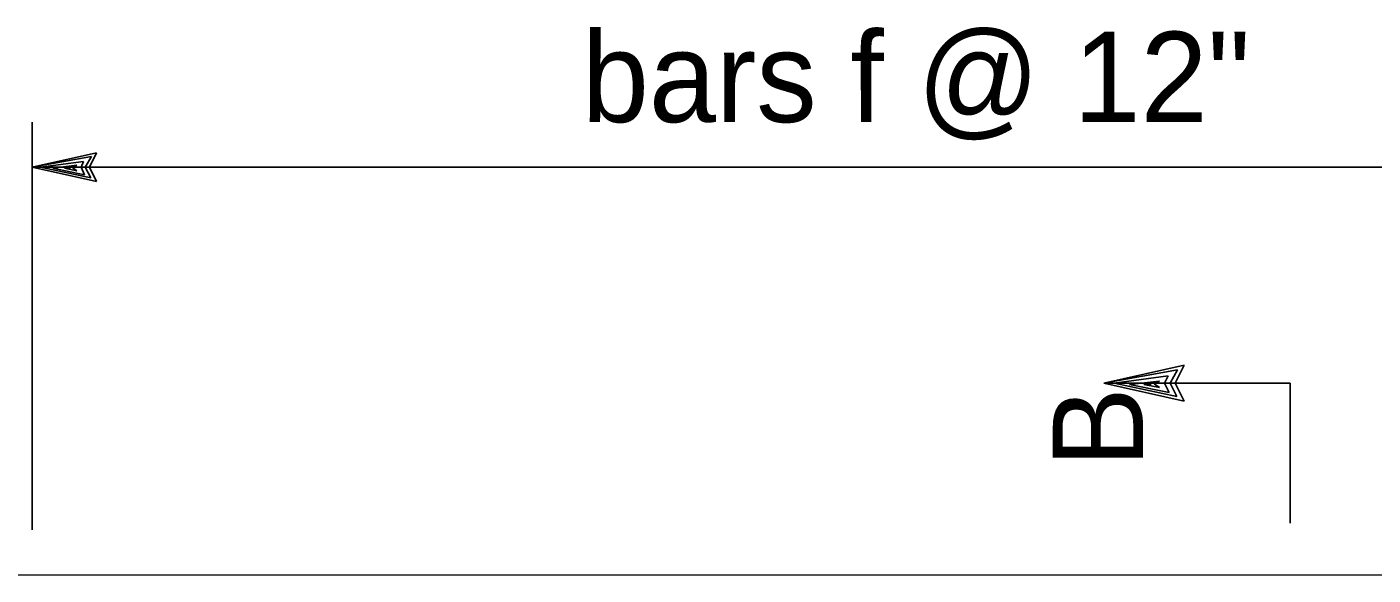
# Model space of a CAD drawing. Extents: x -0.08 to 2.83, y -0.03 to 1.92.
# Drawn here: x 0.7357 to 0.9299, y 1.5819 to 1.661 of the extents above; entities that cross this region are included whole.
import ezdxf

# ---------------------------------------------------------------- set-up
doc = ezdxf.new("R2010")
doc.units = 0
for name, color, linetype in [('50', 7, 'Continuous'), ('55', 7, 'Continuous'), ('57', 7, 'Continuous')]:
    doc.layers.add(name, color=color, linetype=linetype)

msp = doc.modelspace()

# ---------------------------------------------------------------- linework, layer by layer
at = {"layer": '50'}
msp.add_line((0.72312, 1.58193), (1.05185, 1.58196), dxfattribs=at)
at = {"layer": '55'}
for p, q in [((0.73644, 1.58844), (0.73644, 1.64725)), ((0.73644, 1.64074), (0.74572, 1.64283)), ((0.74572, 1.64283), (0.74471, 1.64074)), ((0.73644, 1.64074), (0.74497, 1.64229)), ((0.73766, 1.64074), (0.74384, 1.64154)), ((0.7394, 1.64061), (0.74289, 1.64101)), ((0.74289, 1.64101), (0.74223, 1.64068)), ((0.74384, 1.64154), (0.7435, 1.64074)), ((0.74497, 1.64229), (0.7441, 1.64074)), ((0.73644, 1.64074), (1.03821, 1.64075)), ((0.74572, 1.63866), (0.73644, 1.64074)), ((0.74491, 1.63919), (0.73766, 1.64074)), ((0.74397, 1.63966), (0.7394, 1.64061)), ((0.74289, 1.6402), (0.74108, 1.64061)), ((0.74108, 1.64061), (0.74195, 1.64061)), ((0.74223, 1.64068), (0.74289, 1.6402)), ((0.7435, 1.64074), (0.74397, 1.63966)), ((0.7441, 1.64074), (0.74491, 1.63919)), ((0.74471, 1.64074), (0.74572, 1.63866))]:
    msp.add_line(p, q, dxfattribs=at)
at = {"layer": '57'}
for p, q in [((0.891, 1.60959), (0.90261, 1.61218)), ((0.90261, 1.61218), (0.90132, 1.60959)), ((0.891, 1.60959), (0.90165, 1.61154)), ((0.89253, 1.60959), (0.90028, 1.61064)), ((0.8947, 1.60943), (0.89906, 1.60991)), ((0.89906, 1.60991), (0.89826, 1.60951)), ((0.90028, 1.61064), (0.89979, 1.60959)), ((0.90165, 1.61154), (0.90059, 1.60959)), ((0.91789, 1.60959), (0.891, 1.60959)), ((0.90261, 1.60701), (0.891, 1.60959)), ((0.90157, 1.60766), (0.89253, 1.60959)), ((0.90044, 1.60823), (0.8947, 1.60943)), ((0.89906, 1.60895), (0.8968, 1.60943)), ((0.8968, 1.60943), (0.89786, 1.60943)), ((0.89826, 1.60951), (0.89906, 1.60895)), ((0.89979, 1.60959), (0.90044, 1.60823)), ((0.90059, 1.60959), (0.90157, 1.60766)), ((0.90132, 1.60959), (0.90261, 1.60701)), ((0.91788, 1.58943), (0.91789, 1.60959))]:
    msp.add_line(p, q, dxfattribs=at)

# ---------------------------------------------------------------- texts
for s, height, rotation, p in [('bars f @ 12"', 0.0130208, 0.0033, (0.81572, 1.64724)), ('B', 0.01302, 90, (0.89667, 1.59741))]:
    msp.add_text(s, height=height, rotation=rotation, dxfattribs=at).set_placement(p)

doc.saveas('drawing.dxf')
